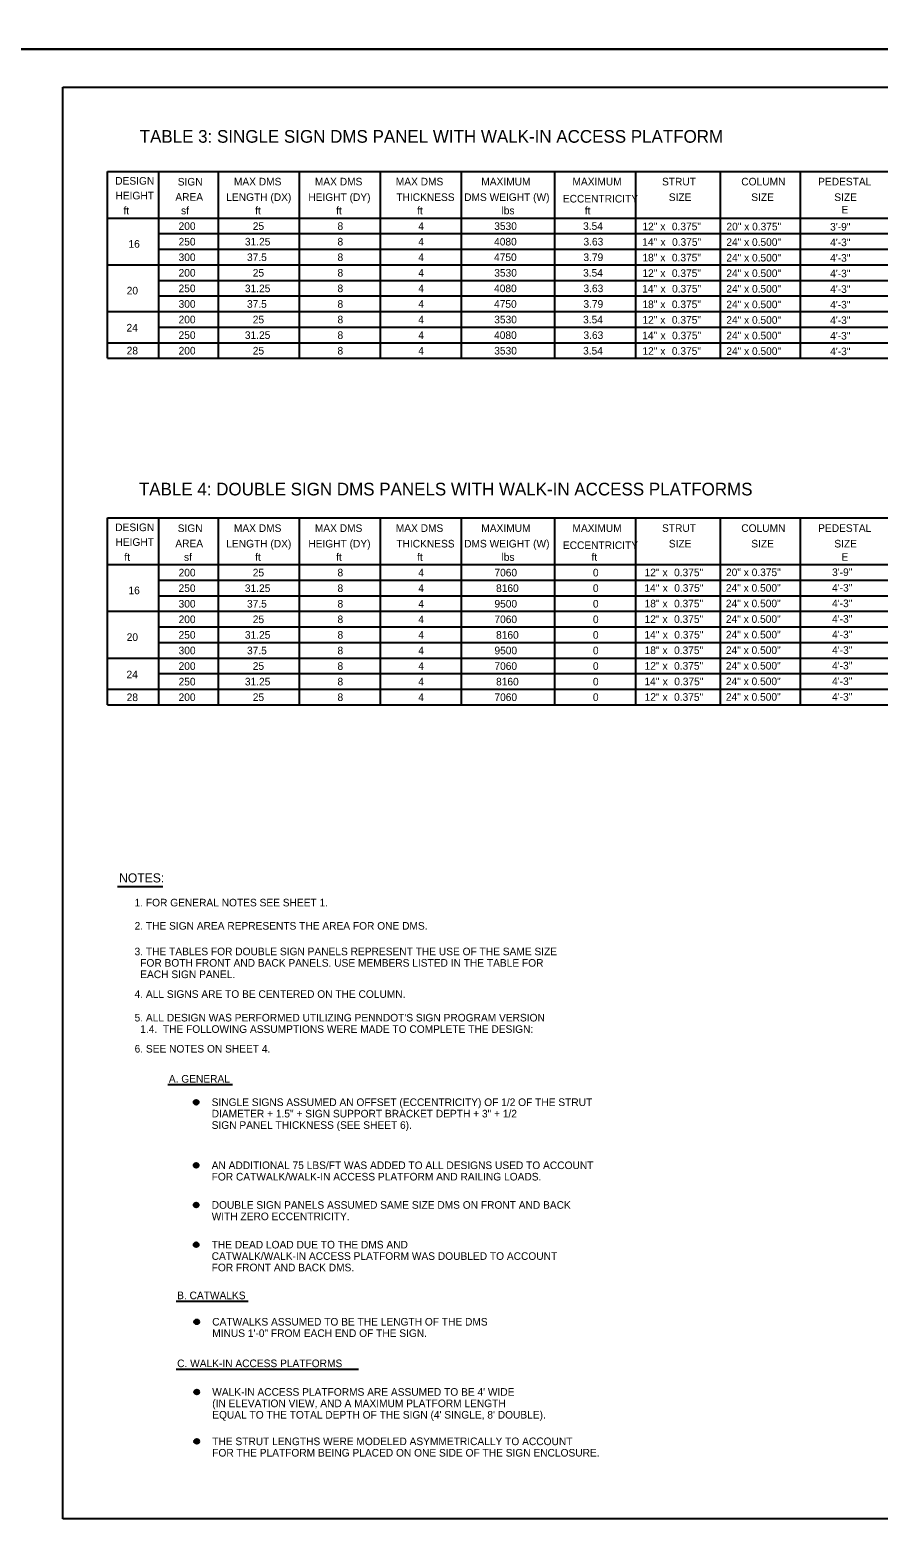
# Model space of a CAD drawing. Extents: x 3829340 to 3831660, y 499389 to 501171.
# Drawn here: x 3830208 to 3830543, y 499991 to 500585 of the extents above; entities that cross this region are included whole.
import ezdxf

# ---------------------------------------------------------------- set-up
doc = ezdxf.new("R2010")
doc.units = 0
for name, color, linetype in [('1', 7, 'Continuous'), ('2', 7, 'Continuous'), ('PLT-BNDY', 7, 'Continuous'), ('TABULATION', 7, 'Continuous'), ('Tabulation Text', 7, 'Continuous')]:
    doc.layers.add(name, color=color, linetype=linetype)

msp = doc.modelspace()

# ---------------------------------------------------------------- linework, layer by layer
at = {"layer": '1'}
for p, q in [((3830242.53, 500247.29), (3830260.33, 500247.29)), ((3830262.32, 500169.28), (3830287.85, 500169.28)), ((3830265.58, 500083.98), (3830294.01, 500083.98)), ((3830265.58, 500057.2), (3830337.49, 500057.2))]:
    msp.add_line(p, q, dxfattribs=at)
for centre, radius in [((3830273.52, 500162.3), 0.96), ((3830273.52, 500162.3), 0.72), ((3830273.52, 500162.3), 0.48), ((3830273.52, 500162.3), 0.24), ((3830273.52, 500162.3), 0.00000192), ((3830273.52, 500137.45), 0.96), ((3830273.52, 500137.45), 0.72), ((3830273.52, 500137.45), 0.48), ((3830273.52, 500137.45), 0.24), ((3830273.52, 500137.45), 0.00000192), ((3830273.52, 500121.81), 0.96), ((3830273.52, 500121.81), 0.72), ((3830273.52, 500121.81), 0.48), ((3830273.52, 500121.81), 0.24), ((3830273.52, 500121.81), 0.00000192), ((3830273.52, 500106.17), 0.96), ((3830273.52, 500106.17), 0.72), ((3830273.52, 500106.17), 0.48), ((3830273.52, 500106.17), 0.24), ((3830273.52, 500106.17), 0.00000192), ((3830273.74, 500075.8), 0.96), ((3830273.74, 500075.8), 0.72), ((3830273.74, 500075.8), 0.48), ((3830273.74, 500075.8), 0.24), ((3830273.74, 500075.8), 0.00000192), ((3830273.74, 500048.15), 0.96), ((3830273.74, 500048.15), 0.72), ((3830273.74, 500048.15), 0.48), ((3830273.74, 500048.15), 0.24), ((3830273.74, 500048.15), 0.00000192), ((3830273.74, 500028.69), 0.96), ((3830273.74, 500028.69), 0.72), ((3830273.74, 500028.69), 0.48), ((3830273.74, 500028.69), 0.24), ((3830273.74, 500028.69), 0.00000192)]:
    msp.add_circle(centre, radius, dxfattribs=at)
at = {"layer": '2'}
for p, q in [((3830220.96, 499998.19), (3830220.96, 500562.19)), ((3830220.96, 500562.19), (3831006.96, 500562.19)), ((3831006.96, 499998.19), (3830220.96, 499998.19))]:
    msp.add_line(p, q, dxfattribs=at)
at = {"layer": 'PLT-BNDY'}
for points in [[(3830180.96, 501171.19), (3831021.96, 501171.19), (3831021.96, 500577.19), (3830180.96, 500577.19)], [(3830180.96, 500577.19), (3831021.96, 500577.19), (3831021.96, 499983.19), (3830180.96, 499983.19)]]:
    msp.add_lwpolyline(points, close=True, dxfattribs=at)
at = {"layer": 'Tabulation Text'}
for p, q in [((3830238.51, 500529.06), (3830629.25, 500529.06)), ((3830238.51, 500455.43), (3830238.51, 500529.06)), ((3830258.76, 500455.43), (3830258.76, 500529.06)), ((3830282.38, 500455.43), (3830282.38, 500529.06)), ((3830314.28, 500455.43), (3830314.28, 500529.06)), ((3830346.19, 500455.43), (3830346.19, 500529.06)), ((3830378.09, 500455.43), (3830378.09, 500529.06)), ((3830414.91, 500455.43), (3830414.91, 500529.06)), ((3830446.81, 500455.43), (3830446.81, 500529.06)), ((3830480.25, 500455.43), (3830480.25, 500529.06)), ((3830511.78, 500455.43), (3830511.78, 500529.06)), ((3830238.51, 500510.65), (3830722.2, 500510.65)), ((3830258.76, 500504.51), (3830864.85, 500504.51)), ((3830258.76, 500498.38), (3830864.85, 500498.38)), ((3830238.51, 500492.24), (3830864.85, 500492.24)), ((3830258.76, 500486.11), (3830864.85, 500486.11)), ((3830258.76, 500479.97), (3830864.85, 500479.97)), ((3830238.51, 500473.84), (3830864.85, 500473.84)), ((3830258.76, 500467.7), (3830864.85, 500467.7)), ((3830238.51, 500461.56), (3830864.85, 500461.56)), ((3830238.51, 500455.43), (3830864.85, 500455.43)), ((3830238.51, 500392.54), (3830629.25, 500392.54)), ((3830238.51, 500318.91), (3830238.51, 500392.54)), ((3830258.76, 500318.91), (3830258.76, 500392.54)), ((3830282.38, 500318.91), (3830282.38, 500392.54)), ((3830314.28, 500318.91), (3830314.28, 500392.54)), ((3830346.19, 500318.91), (3830346.19, 500392.54)), ((3830378.09, 500318.91), (3830378.09, 500392.54)), ((3830414.91, 500318.91), (3830414.91, 500392.54)), ((3830446.81, 500318.91), (3830446.81, 500392.54)), ((3830480.25, 500318.91), (3830480.25, 500392.54)), ((3830511.78, 500318.91), (3830511.78, 500392.54)), ((3830238.51, 500374.13), (3830722.2, 500374.13)), ((3830258.76, 500368), (3830864.85, 500368)), ((3830258.76, 500361.86), (3830864.85, 500361.86)), ((3830238.51, 500355.73), (3830864.85, 500355.73)), ((3830258.76, 500349.59), (3830864.85, 500349.59)), ((3830258.76, 500343.45), (3830864.85, 500343.45)), ((3830238.51, 500337.32), (3830864.85, 500337.32)), ((3830258.76, 500331.18), (3830864.85, 500331.18)), ((3830238.51, 500325.05), (3830864.85, 500325.05)), ((3830238.51, 500318.91), (3830864.85, 500318.91))]:
    msp.add_line(p, q, dxfattribs=at)

# ---------------------------------------------------------------- texts
at = {"layer": '1'}
for s, height, p in [('TABLE 3: SINGLE SIGN DMS PANEL WITH WALK-IN ACCESS PLATFORM', 4.9999, (3830251.26, 500540.33)), ('TABLE 4: DOUBLE SIGN DMS PANELS WITH WALK-IN ACCESS PLATFORMS', 4.9999, (3830250.94, 500401.38)), ('NOTES:', 3.57, (3830243.15, 500248.91)), ('1. FOR GENERAL NOTES SEE SHEET 1.', 2.9999, (3830249.25, 500239.46)), ('2. THE SIGN AREA REPRESENTS THE AREA FOR ONE DMS.', 2.9999, (3830249.25, 500230.3)), ('3. THE TABLES FOR DOUBLE SIGN PANELS REPRESENT THE USE OF THE SAME SIZE', 2.9999, (3830249.25, 500220.21)), ('  FOR BOTH FRONT AND BACK PANELS. USE MEMBERS LISTED IN THE TABLE FOR', 2.9999, (3830249.25, 500215.71)), ('  EACH SIGN PANEL.', 2.9999, (3830249.25, 500211.21)), ('4. ALL SIGNS ARE TO BE CENTERED ON THE COLUMN.  ', 2.9999, (3830249.25, 500203.43)), ("5. ALL DESIGN WAS PERFORMED UTILIZING PENNDOT'S SIGN PROGRAM VERSION", 2.9999, (3830249.25, 500194.13)), ('  1.4.  THE FOLLOWING ASSUMPTIONS WERE MADE TO COMPLETE THE DESIGN:', 2.9999, (3830249.25, 500189.63)), ('6. SEE NOTES ON SHEET 4.', 2.9999, (3830249.25, 500181.88)), ('A. GENERAL', 3, (3830262.75, 500170.02)), ('SINGLE SIGNS ASSUMED AN OFFSET (ECCENTRICITY) OF 1/2 OF THE STRUT', 2.9999, (3830279.63, 500160.82)), ('SIGN PANEL THICKNESS (SEE SHEET 6).', 2.9999, (3830279.63, 500151.82)), ('DIAMETER + 1.5" + SIGN SUPPORT BRACKET DEPTH + 3" + 1/2', 2.9999, (3830279.63, 500156.32)), ('AN ADDITIONAL 75 LBS/FT WAS ADDED TO ALL DESIGNS USED TO ACCOUNT ', 2.9999, (3830279.63, 500135.98)), ('FOR CATWALK/WALK-IN ACCESS PLATFORM AND RAILING LOADS.', 2.9999, (3830279.63, 500131.48)), ('WITH ZERO ECCENTRICITY. ', 2.9999, (3830279.63, 500115.84)), ('DOUBLE SIGN PANELS ASSUMED SAME SIZE DMS ON FRONT AND BACK', 2.9999, (3830279.63, 500120.34)), ('THE DEAD LOAD DUE TO THE DMS AND', 2.9999, (3830279.63, 500104.7)), ('CATWALK/WALK-IN ACCESS PLATFORM WAS DOUBLED TO ACCOUNT', 2.9999, (3830279.63, 500100.2)), ('FOR FRONT AND BACK DMS.', 2.9999, (3830279.63, 500095.7)), ('B. CATWALKS', 2.9999, (3830266.02, 500084.71)), ('CATWALKS ASSUMED TO BE THE LENGTH OF THE DMS', 2.9999, (3830279.85, 500074.32)), ('MINUS 1\'-0" FROM EACH END OF THE SIGN.', 2.9999, (3830279.85, 500069.82)), ('C. WALK-IN ACCESS PLATFORMS', 2.9999, (3830266.02, 500057.94)), ("WALK-IN ACCESS PLATFORMS ARE ASSUMED TO BE 4' WIDE", 2.9999, (3830279.85, 500046.67)), ('(IN ELEVATION VIEW, AND A MAXIMUM PLATFORM LENGTH ', 2.9999, (3830279.85, 500042.17)), ("EQUAL TO THE TOTAL DEPTH OF THE SIGN (4' SINGLE, 8' DOUBLE).  ", 2.9999, (3830279.85, 500037.67)), ('THE STRUT LENGTHS WERE MODELED ASYMMETRICALLY TO ACCOUNT', 2.9999, (3830279.85, 500027.21)), ('FOR THE PLATFORM BEING PLACED ON ONE SIDE OF THE SIGN ENCLOSURE.', 2.9999, (3830279.85, 500022.71))]:
    msp.add_text(s, height=height, dxfattribs=at).set_placement(p)
at = {"layer": 'TABULATION'}
for s, height, p in [('DESIGN', 3, (3830241.62, 500523.82)), ('SIGN', 3, (3830266.25, 500523.47)), ('MAX DMS', 3, (3830288.39, 500523.52)), ('MAX DMS', 3, (3830320.3, 500523.52)), ('MAX DMS', 3, (3830352.2, 500523.52)), ('MAXIMUM ', 3, (3830385.91, 500523.52)), ('MAXIMUM', 3, (3830421.84, 500523.52)), ('STRUT', 3, (3830457.14, 500523.52)), ('COLUMN', 3, (3830488.38, 500523.52)), ('PEDESTAL', 3, (3830518.67, 500523.52)), ('HEIGHT', 3, (3830241.71, 500518.02)), ('AREA', 3, (3830265.31, 500517.47)), ('LENGTH (DX)', 2.9996, (3830285.4, 500517.39)), ('HEIGHT (DY)', 2.9996, (3830317.73, 500517.39)), ('THICKNESS', 3, (3830352.42, 500517.38)), ('DMS WEIGHT (W)', 2.9996, (3830379.14, 500517.39)), ('ECCENTRICITY', 2.9996, (3830418.05, 500516.79)), ('SIZE', 3, (3830459.82, 500517.38)), ('SIZE', 3, (3830492.31, 500517.38)), ('SIZE', 3, (3830525.04, 500517.38)), ('DESIGN', 3, (3830241.62, 500387.31)), ('SIGN', 3, (3830266.25, 500386.95)), ('MAX DMS', 3, (3830288.39, 500387)), ('MAX DMS', 3, (3830320.3, 500387)), ('MAX DMS', 3, (3830352.2, 500387)), ('MAXIMUM ', 3, (3830385.91, 500387)), ('MAXIMUM', 3, (3830421.84, 500387)), ('STRUT', 3, (3830457.14, 500387)), ('COLUMN', 3, (3830488.38, 500387)), ('PEDESTAL', 3, (3830518.67, 500387)), ('HEIGHT', 3, (3830241.71, 500381.5)), ('AREA', 3, (3830265.31, 500380.95)), ('LENGTH (DX)', 2.9996, (3830285.4, 500380.87)), ('HEIGHT (DY)', 2.9996, (3830317.73, 500380.87)), ('THICKNESS', 3, (3830352.42, 500380.87)), ('DMS WEIGHT (W)', 2.9996, (3830379.14, 500380.87)), ('ECCENTRICITY', 2.9996, (3830418.05, 500380.27)), ('SIZE', 3, (3830459.82, 500380.87)), ('SIZE', 3, (3830492.31, 500380.87)), ('SIZE', 3, (3830525.04, 500380.87))]:
    msp.add_text(s, height=height, dxfattribs=at).set_placement(p)
at = {"layer": 'Tabulation Text'}
for s, height, p in [('ft', 3, (3830244.84, 500512.12)), ('sf', 3, (3830267.55, 500512.12)), ('ft', 3, (3830296.76, 500512.12)), ('ft', 3, (3830328.67, 500512.12)), ('ft', 3, (3830360.57, 500512.12)), ('lbs', 3, (3830393.88, 500512.12)), ('ft', 3, (3830426.68, 500512.12)), ('E', 3, (3830527.84, 500512.47)), ('200', 3, (3830266.59, 500505.99)), ('25', 3, (3830295.83, 500505.99)), ('8', 3, (3830329.23, 500505.99)), ('4', 3, (3830361.07, 500505.99)), ('3530', 3, (3830391.01, 500505.99)), ('3.54', 3, (3830426.03, 500505.99)), ('12"', 3, (3830449.4, 500505.86)), (' x', 3, (3830455.35, 500505.86)), (' 0.375"', 3, (3830459.91, 500505.86)), ('20" x 0.375"', 2.9996, (3830482.53, 500505.81)), ('3\'-9"', 3, (3830523.4, 500505.72)), ('16', 3, (3830246.85, 500498.98)), ('250', 3, (3830266.58, 500499.85)), ('31.25', 3, (3830292.72, 500499.85)), ('8', 3, (3830329.23, 500499.85)), ('4', 3, (3830361.07, 500499.85)), ('4080', 3, (3830390.95, 500499.85)), ('3.63', 3, (3830426.17, 500499.85)), ('14"', 3, (3830449.33, 500499.72)), (' x', 3, (3830455.42, 500499.72)), (' 0.375"', 3, (3830459.98, 500499.72)), ('24" x 0.500"', 2.9996, (3830482.48, 500499.68)), ('4\'-3"', 3, (3830523.4, 500499.59)), ('300', 3, (3830266.59, 500493.72)), ('37.5', 3, (3830293.56, 500493.72)), ('8', 3, (3830329.23, 500493.72)), ('4', 3, (3830361.07, 500493.72)), ('4750', 3, (3830390.93, 500493.72)), ('3.79', 3, (3830426.16, 500493.72)), ('18"', 3, (3830449.4, 500493.58)), (' x', 3, (3830455.35, 500493.58)), (' 0.375"', 3, (3830459.91, 500493.58)), ('24" x 0.500"', 2.9996, (3830482.48, 500493.54)), ('4\'-3"', 3, (3830523.4, 500493.45)), ('200', 3, (3830266.59, 500487.58)), ('25', 3, (3830295.83, 500487.58)), ('8', 3, (3830329.23, 500487.58)), ('4', 3, (3830361.07, 500487.58)), ('3530', 3, (3830391.01, 500487.58)), ('3.54', 3, (3830426.03, 500487.58)), ('12"', 3, (3830449.4, 500487.45)), (' x', 3, (3830455.35, 500487.45)), (' 0.375"', 3, (3830459.91, 500487.45)), ('24" x 0.500"', 2.9996, (3830482.48, 500487.41)), ('4\'-3"', 3, (3830523.4, 500487.32)), ('20', 3, (3830246.14, 500480.57)), ('250', 3, (3830266.58, 500481.45)), ('31.25', 3, (3830292.72, 500481.45)), ('8', 3, (3830329.23, 500481.45)), ('4', 3, (3830361.07, 500481.45)), ('4080', 3, (3830390.95, 500481.45)), ('3.63', 3, (3830426.17, 500481.45)), ('14"', 3, (3830449.33, 500481.31)), (' x', 3, (3830455.42, 500481.31)), (' 0.375"', 3, (3830459.98, 500481.31)), ('24" x 0.500"', 2.9996, (3830482.48, 500481.27)), ('4\'-3"', 3, (3830523.4, 500481.18)), ('300', 3, (3830266.59, 500475.31)), ('37.5', 3, (3830293.56, 500475.31)), ('8', 3, (3830329.23, 500475.31)), ('4', 3, (3830361.07, 500475.31)), ('4750', 3, (3830390.93, 500475.31)), ('3.79', 3, (3830426.16, 500475.31)), ('18"', 3, (3830449.4, 500475.18)), (' x', 3, (3830455.35, 500475.18)), (' 0.375"', 3, (3830459.91, 500475.18)), ('24" x 0.500"', 2.9996, (3830482.48, 500475.14)), ('4\'-3"', 3, (3830523.4, 500475.04)), ('24', 3, (3830246.06, 500465.95)), ('200', 3, (3830266.59, 500469.18)), ('25', 3, (3830295.83, 500469.18)), ('8', 3, (3830329.23, 500469.18)), ('4', 3, (3830361.07, 500469.18)), ('3530', 3, (3830391.01, 500469.18)), ('3.54', 3, (3830426.03, 500469.18)), ('12"', 3, (3830449.4, 500469.04)), (' x', 3, (3830455.35, 500469.04)), (' 0.375"', 3, (3830459.91, 500469.04)), ('24" x 0.500"', 2.9996, (3830482.48, 500469)), ('4\'-3"', 3, (3830523.4, 500468.91)), ('250', 3, (3830266.58, 500463.04)), ('31.25', 3, (3830292.72, 500463.04)), ('8', 3, (3830329.23, 500463.04)), ('4', 3, (3830361.07, 500463.04)), ('4080', 3, (3830390.95, 500463.04)), ('3.63', 3, (3830426.17, 500463.04)), ('14"', 3, (3830449.33, 500462.91)), (' x', 3, (3830455.42, 500462.91)), (' 0.375"', 3, (3830459.98, 500462.91)), ('24" x 0.500"', 2.9996, (3830482.48, 500462.87)), ('4\'-3"', 3, (3830523.4, 500462.77)), ('28', 3, (3830246.13, 500456.94)), ('200', 3, (3830266.59, 500456.9)), ('25', 3, (3830295.83, 500456.9)), ('8', 3, (3830329.23, 500456.9)), ('4', 3, (3830361.07, 500456.9)), ('3530', 3, (3830391.01, 500456.9)), ('3.54', 3, (3830426.03, 500456.9)), ('12"', 3, (3830449.4, 500456.77)), (' x', 3, (3830455.35, 500456.77)), (' 0.375"', 3, (3830459.91, 500456.77)), ('24" x 0.500"', 2.9996, (3830482.48, 500456.73)), ('4\'-3"', 3, (3830523.4, 500456.64)), ('ft', 3, (3830245.21, 500375.61)), ('sf', 3, (3830268.71, 500375.61)), ('ft', 3, (3830296.76, 500375.61)), ('ft', 3, (3830328.67, 500375.61)), ('ft', 3, (3830360.57, 500375.61)), ('lbs', 3, (3830393.88, 500375.61)), ('ft', 3, (3830429.32, 500375.61)), ('E', 3, (3830527.84, 500375.62)), ('200', 3, (3830266.59, 500369.47)), ('25', 3, (3830295.83, 500369.47)), ('8', 3, (3830329.23, 500369.47)), ('4', 3, (3830361.07, 500369.47)), ('7060', 3, (3830391.08, 500369.47)), ('0', 3, (3830429.9, 500369.47)), ('12"', 3, (3830450.27, 500369.54)), (' x', 3, (3830456.22, 500369.54)), (' 0.375"', 3, (3830460.78, 500369.54)), ('20" x 0.375"', 2.9996, (3830482.36, 500369.59)), ('3\'-9"', 3, (3830524.16, 500369.63)), ('16', 3, (3830246.85, 500362.46)), ('250', 3, (3830266.58, 500363.34)), ('31.25', 3, (3830292.72, 500363.34)), ('8', 3, (3830329.23, 500363.34)), ('4', 3, (3830361.07, 500363.34)), ('8160', 3, (3830391.73, 500363.34)), ('0', 3, (3830429.9, 500363.34)), ('14"', 3, (3830450.2, 500363.41)), (' x', 3, (3830456.29, 500363.41)), (' 0.375"', 3, (3830460.85, 500363.41)), ('24" x 0.500"', 2.9996, (3830482.32, 500363.45)), ('4\'-3"', 3, (3830524.16, 500363.5)), ('300', 3, (3830266.59, 500357.2)), ('37.5', 3, (3830293.56, 500357.2)), ('8', 3, (3830329.23, 500357.2)), ('4', 3, (3830361.07, 500357.2)), ('9500', 3, (3830391.09, 500357.2)), ('0', 3, (3830429.9, 500357.2)), ('18"', 3, (3830450.27, 500357.27)), (' x', 3, (3830456.22, 500357.27)), (' 0.375"', 3, (3830460.78, 500357.27)), ('24" x 0.500"', 2.9996, (3830482.32, 500357.32)), ('4\'-3"', 3, (3830524.16, 500357.36)), ('200', 3, (3830266.59, 500351.07)), ('25', 3, (3830295.83, 500351.07)), ('8', 3, (3830329.23, 500351.07)), ('4', 3, (3830361.07, 500351.07)), ('7060', 3, (3830391.08, 500351.07)), ('0', 3, (3830429.9, 500351.07)), ('12"', 3, (3830450.27, 500351.14)), (' x', 3, (3830456.22, 500351.14)), (' 0.375"', 3, (3830460.78, 500351.14)), ('24" x 0.500"', 2.9996, (3830482.32, 500351.18)), ('4\'-3"', 3, (3830524.16, 500351.22)), ('20', 3, (3830246.14, 500344.05)), ('250', 3, (3830266.58, 500344.93)), ('31.25', 3, (3830292.72, 500344.93)), ('8', 3, (3830329.23, 500344.93)), ('4', 3, (3830361.07, 500344.93)), ('8160', 3, (3830391.73, 500344.93)), ('0', 3, (3830429.9, 500344.93)), ('14"', 3, (3830450.2, 500345)), (' x', 3, (3830456.29, 500345)), (' 0.375"', 3, (3830460.85, 500345)), ('24" x 0.500"', 2.9996, (3830482.32, 500345.05)), ('4\'-3"', 3, (3830524.16, 500345.09)), ('300', 3, (3830266.59, 500338.79)), ('37.5', 3, (3830293.56, 500338.79)), ('8', 3, (3830329.23, 500338.79)), ('4', 3, (3830361.07, 500338.79)), ('9500', 3, (3830391.09, 500338.79)), ('0', 3, (3830429.9, 500338.79)), ('18"', 3, (3830450.27, 500338.87)), (' x', 3, (3830456.22, 500338.87)), (' 0.375"', 3, (3830460.78, 500338.87)), ('24" x 0.500"', 2.9996, (3830482.32, 500338.91)), ('4\'-3"', 3, (3830524.16, 500338.95)), ('24', 3, (3830246.06, 500329.33)), ('200', 3, (3830266.59, 500332.66)), ('25', 3, (3830295.83, 500332.66)), ('8', 3, (3830329.23, 500332.66)), ('4', 3, (3830361.07, 500332.66)), ('7060', 3, (3830391.08, 500332.66)), ('0', 3, (3830429.9, 500332.66)), ('12"', 3, (3830450.27, 500332.73)), (' x', 3, (3830456.22, 500332.73)), (' 0.375"', 3, (3830460.78, 500332.73)), ('24" x 0.500"', 2.9996, (3830482.32, 500332.78)), ('4\'-3"', 3, (3830524.16, 500332.82)), ('250', 3, (3830266.58, 500326.52)), ('31.25', 3, (3830292.72, 500326.52)), ('8', 3, (3830329.23, 500326.52)), ('4', 3, (3830361.07, 500326.52)), ('8160', 3, (3830391.73, 500326.52)), ('0', 3, (3830429.9, 500326.52)), ('14"', 3, (3830450.2, 500326.59)), (' x', 3, (3830456.29, 500326.59)), (' 0.375"', 3, (3830460.85, 500326.59)), ('24" x 0.500"', 2.9996, (3830482.32, 500326.64)), ('4\'-3"', 3, (3830524.16, 500326.68)), ('28', 3, (3830246.13, 500320.36)), ('200', 3, (3830266.59, 500320.39)), ('25', 3, (3830295.83, 500320.39)), ('8', 3, (3830329.23, 500320.39)), ('4', 3, (3830361.07, 500320.39)), ('7060', 3, (3830391.08, 500320.39)), ('0', 3, (3830429.9, 500320.39)), ('12"', 3, (3830450.27, 500320.46)), (' x', 3, (3830456.22, 500320.46)), (' 0.375"', 3, (3830460.78, 500320.46)), ('24" x 0.500"', 2.9996, (3830482.32, 500320.51)), ('4\'-3"', 3, (3830524.16, 500320.55))]:
    msp.add_text(s, height=height, dxfattribs=at).set_placement(p)

doc.saveas('drawing.dxf')
